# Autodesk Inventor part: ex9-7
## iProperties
Author: Administrator
Created: 2001-09
Part Number: ex9-7
Document SubType Name: Sheet Metal
Designer: Administrator
Control State: 0
Master: False
Checked Out: False
PropertySet Name: Design Tracking Control
Length Units: 11272
Angle Units: 11279
Time Units: 11290
Mass Units: 11286
Shininess: 3
Angle Display Precision: 2
Document Length Units: 11272
Document Angle Units: 11286
Document Time Units: 11279
Document Mass Units: 11290
Document Length Units Precision: 3
Document Angle Units Precision: 2
Compacted: False
PropertySet Name: _Private Model Information
Density: 0.0
Volumn: 0.0
Area: 0.0
PropertySet Name: Model Information
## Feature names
1. Plate1
2. Bend1
3. Plate2
4. Bend2
5. Cut1
